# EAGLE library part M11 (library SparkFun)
Header 11 Standard 11-pin 0.1" header. Use with straight break away headers (SKU : PType-HD), right angle break away headers (PType-HD-RightAngle), swiss pins (PType-30F), machine pins (PType-MP), and female headers (PType-FH). Molex polarized connector foot print use with SKU : Con-Hdr with associated crimp pins and housings.
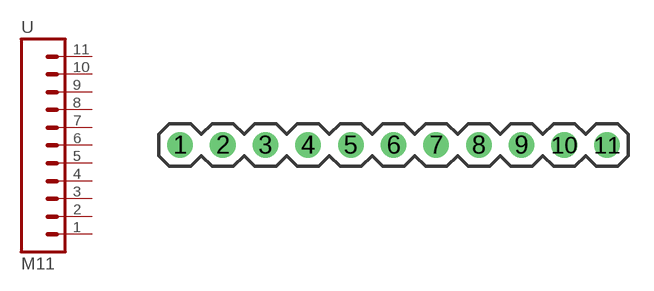
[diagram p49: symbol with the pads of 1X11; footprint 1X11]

Designator prefix -

## M11PTH  [1X11]
1  1  pas
2  2  pas
3  3  pas
4  4  pas
5  5  pas
6  6  pas
7  7  pas
8  8  pas
9  9  pas
10  10  pas
11  11  pas

## Footprint 1X11 (pad centres in mm)
drill 1.016 round: 1 0,0; 2 2.54,0; 3 5.08,0; 4 7.62,0; 5 10.16,0; 6 12.7,0; 7 15.24,0; 8 17.78,0; 9 20.32,0; 10 22.86,0; 11 25.4,0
